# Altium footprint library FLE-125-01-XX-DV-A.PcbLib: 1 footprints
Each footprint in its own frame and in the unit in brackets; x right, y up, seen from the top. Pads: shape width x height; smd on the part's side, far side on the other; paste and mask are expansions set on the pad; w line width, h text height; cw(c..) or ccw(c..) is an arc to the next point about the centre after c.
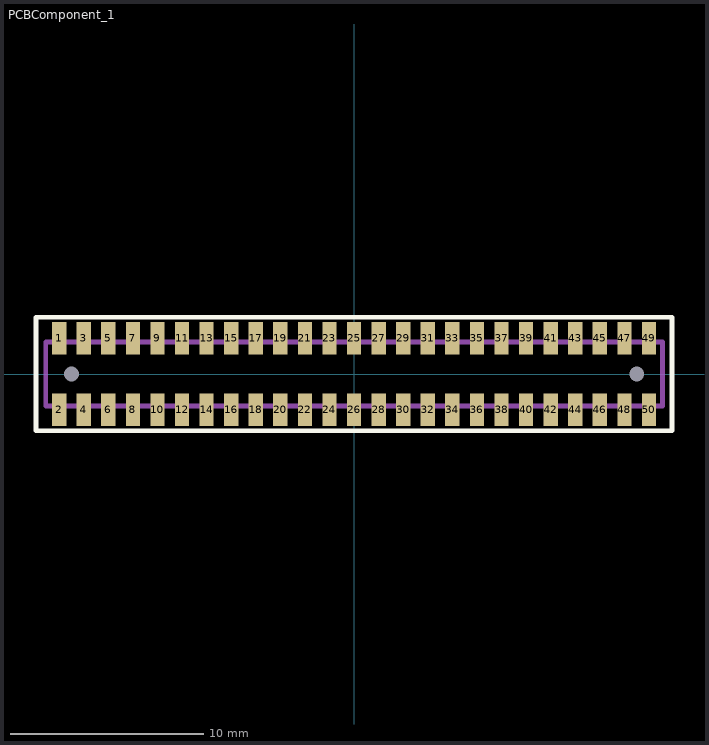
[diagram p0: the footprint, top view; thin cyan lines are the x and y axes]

## PCBComponent_1 [mil]
pads (52):
  rect 29x66 smd mask+2: 1(-600,72.5) 2(-600,-72.5) 3(-550,72.5) 4(-550,-72.5) 5(-500,72.5) 6(-500,-72.5) 7(-450,72.5) 8(-450,-72.5) 9(-400,72.5) 10(-400,-72.5) 11(-350,72.5) 12(-350,-72.5) 13(-300,72.5) 14(-300,-72.5) 15(-250,72.5) 16(-250,-72.5) 17(-200,72.5) 18(-200,-72.5) 19(-150,72.5) 20(-150,-72.5) 21(-100,72.5) 22(-100,-72.5) 23(-50,72.5) 24(-50,-72.5) 25(0,72.5) 26(0,-72.5) 27(50,72.5) 28(50,-72.5) 29(100,72.5) 30(100,-72.5) 31(150,72.5) 32(150,-72.5) 33(200,72.5) 34(200,-72.5) 35(250,72.5) 36(250,-72.5) 37(300,72.5) 38(300,-72.5) 39(350,72.5) 40(350,-72.5) 41(400,72.5) 42(400,-72.5) 43(450,72.5) 44(450,-72.5) 45(500,72.5) 46(500,-72.5) 47(550,72.5) 48(550,-72.5) 49(600,72.5) 50(600,-72.5)
  round 0 hole 30 unplated: 51(-575,0) 52(575,0)
Top Overlay:
  lines w10: -647.5,-115.5 647.25,-115.5 647.25,115.5 -647.5,115.5 -647.5,-115.5
Mechanical 1:
  lines w10: -627.25,-65.5 627.25,-65.5 627.25,65.5 -627.25,65.5 -627.25,-65.5
  text "J1" at -17.57,-18 h30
